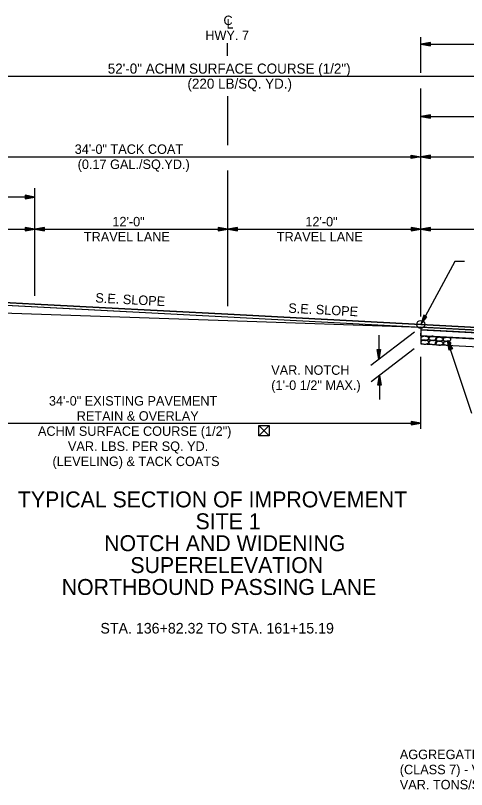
# Model space of a CAD drawing. Extents: x 1398183 to 1398373, y 1967240 to 1968889.
# Drawn here: x 1398229.85 to 1398257.9, y 1968531.11 to 1968579.23 of the extents above; entities that cross this region are included whole.
import ezdxf

# ---------------------------------------------------------------- set-up
doc = ezdxf.new("R2010")
doc.units = 0
for name, color, linetype in [('1', 7, 'Continuous'), ('10', 7, 'Continuous'), ('19', 7, 'Continuous'), ('42', 7, 'Continuous'), ('7', 7, 'Continuous'), ('Level 1', 7, 'Continuous'), ('Level 9', 7, 'Continuous')]:
    doc.layers.add(name, color=color, linetype=linetype)

# ---------------------------------------------------------------- blocks, each defined once
blk = doc.blocks.new('ROCKS')
at = {"layer": '1'}
blk.add_spline([(0.013, 0.06), (0.053, 0.053), (0.107, 0.033), (0.133, 0.013), (0.133, -0.007), (0.12, -0.033), (0.107, -0.04), (0.073, -0.053), (0.033, -0.067), (0.013, -0.067), (-0.02, -0.06), (-0.06, -0.053), (-0.087, -0.047), (-0.113, -0.02), (-0.113, -0.007), (-0.107, 0.02), (-0.087, 0.033), (-0.067, 0.047), (-0.033, 0.053), (-0.02, 0.06), (0.013, 0.06)], degree=3, dxfattribs=at)

msp = doc.modelspace()

# ---------------------------------------------------------------- linework, layer by layer
at = {"layer": '10'}
for p, q in [((1398245.618, 1968553.733), (1398244.977, 1968553.092)), ((1398244.977, 1968553.733), (1398245.618, 1968553.092)), ((1398245.236, 1968553.092), (1398245.225, 1968553.092))]:
    msp.add_line(p, q, dxfattribs=at)
msp.add_lwpolyline([(1398245.225, 1968553.092), (1398244.977, 1968553.092), (1398244.977, 1968553.733), (1398245.618, 1968553.733), (1398245.618, 1968553.092), (1398245.236, 1968553.092)], dxfattribs=at)
at = {"layer": '19'}
for p, q in [((1398255.052, 1968575.667), (1398255.052, 1968577.893)), ((1398255.652, 1968577.55), (1398255.052, 1968577.446)), ((1398255.052, 1968577.446), (1398255.652, 1968577.34)), ((1398255.052, 1968577.446), (1398279.092, 1968577.446)), ((1398255.652, 1968577.495), (1398255.212, 1968577.461)), ((1398255.212, 1968577.431), (1398255.652, 1968577.39)), ((1398255.652, 1968577.34), (1398255.652, 1968577.55)), ((1398272.994, 1968575.446), (1398220.994, 1968575.446)), ((1398255.052, 1968560.522), (1398255.052, 1968574.682)), ((1398255.652, 1968573.05), (1398255.052, 1968572.946)), ((1398255.052, 1968572.946), (1398285.602, 1968572.946)), ((1398255.052, 1968572.946), (1398255.652, 1968572.84)), ((1398255.652, 1968572.995), (1398255.212, 1968572.961)), ((1398255.212, 1968572.931), (1398255.652, 1968572.89)), ((1398255.652, 1968572.84), (1398255.652, 1968573.05)), ((1398220.994, 1968570.446), (1398282.96, 1968570.446)), ((1398254.452, 1968570.341), (1398254.452, 1968570.551)), ((1398254.452, 1968570.551), (1398255.052, 1968570.446)), ((1398254.452, 1968570.496), (1398254.892, 1968570.461)), ((1398255.052, 1968570.446), (1398254.452, 1968570.341)), ((1398254.892, 1968570.431), (1398254.452, 1968570.391)), ((1398255.652, 1968570.551), (1398255.052, 1968570.446)), ((1398255.052, 1968570.446), (1398255.652, 1968570.341)), ((1398255.652, 1968570.496), (1398255.212, 1968570.461)), ((1398255.212, 1968570.431), (1398255.652, 1968570.391)), ((1398255.652, 1968570.341), (1398255.652, 1968570.551)), ((1398231.052, 1968561.794), (1398231.052, 1968568.492)), ((1398231.052, 1968567.946), (1398207.052, 1968567.946)), ((1398230.452, 1968568.051), (1398230.452, 1968567.841)), ((1398231.052, 1968567.946), (1398230.452, 1968568.051)), ((1398230.892, 1968567.961), (1398230.452, 1968567.996)), ((1398230.452, 1968567.841), (1398231.052, 1968567.946)), ((1398230.452, 1968567.891), (1398230.892, 1968567.931)), ((1398221.052, 1968565.946), (1398231.052, 1968565.946)), ((1398230.452, 1968566.051), (1398230.452, 1968565.841)), ((1398231.052, 1968565.946), (1398230.452, 1968566.051)), ((1398230.892, 1968565.961), (1398230.452, 1968565.996)), ((1398230.452, 1968565.841), (1398231.052, 1968565.946)), ((1398230.452, 1968565.891), (1398230.892, 1968565.931)), ((1398231.652, 1968566.05), (1398231.052, 1968565.946)), ((1398231.052, 1968565.946), (1398243.052, 1968565.946)), ((1398231.052, 1968565.946), (1398231.652, 1968565.84)), ((1398231.652, 1968565.995), (1398231.212, 1968565.961)), ((1398231.212, 1968565.931), (1398231.652, 1968565.89)), ((1398231.652, 1968565.84), (1398231.652, 1968566.05)), ((1398242.452, 1968566.051), (1398242.452, 1968565.841)), ((1398243.052, 1968565.946), (1398242.452, 1968566.051)), ((1398242.892, 1968565.961), (1398242.452, 1968565.996)), ((1398242.452, 1968565.841), (1398243.052, 1968565.946)), ((1398242.452, 1968565.891), (1398242.892, 1968565.931)), ((1398243.652, 1968566.05), (1398243.052, 1968565.946)), ((1398243.052, 1968565.946), (1398243.652, 1968565.84)), ((1398243.052, 1968565.946), (1398255.052, 1968565.946)), ((1398243.652, 1968565.995), (1398243.212, 1968565.961)), ((1398243.212, 1968565.931), (1398243.652, 1968565.89)), ((1398243.652, 1968565.84), (1398243.652, 1968566.05)), ((1398254.452, 1968566.051), (1398254.452, 1968565.841)), ((1398255.052, 1968565.946), (1398254.452, 1968566.051)), ((1398254.892, 1968565.961), (1398254.452, 1968565.996)), ((1398254.452, 1968565.841), (1398255.052, 1968565.946)), ((1398254.452, 1968565.891), (1398254.892, 1968565.931)), ((1398255.652, 1968566.05), (1398255.052, 1968565.946)), ((1398255.052, 1968565.946), (1398255.652, 1968565.84)), ((1398255.052, 1968565.946), (1398267.052, 1968565.946)), ((1398255.652, 1968565.995), (1398255.212, 1968565.961)), ((1398255.212, 1968565.931), (1398255.652, 1968565.89)), ((1398255.652, 1968565.84), (1398255.652, 1968566.05)), ((1398255.236, 1968560.602), (1398255.052, 1968560.022)), ((1398255.275, 1968560.578), (1398255.113, 1968560.172)), ((1398255.421, 1968560.506), (1398255.236, 1968560.602)), ((1398255.052, 1968560.022), (1398255.421, 1968560.506)), ((1398255.134, 1968560.158), (1398255.372, 1968560.526)), ((1398255.052, 1968559.856), (1398255.052, 1968559.689)), ((1398255.052, 1968559.689), (1398255.052, 1968559.314)), ((1398255.052, 1968559.689), (1398267.222, 1968559.046)), ((1398266.472, 1968559.085), (1398255.511, 1968559.661)), ((1398254.655, 1968559.55), (1398251.953, 1968557.481)), ((1398252.454, 1968559.365), (1398252.454, 1968557.865)), ((1398255.052, 1968559.314), (1398255.052, 1968558.814)), ((1398267.411, 1968558.667), (1398255.052, 1968559.314)), ((1398256.82, 1968558.432), (1398256.719, 1968559.031)), ((1398256.719, 1968559.031), (1398257.017, 1968558.5)), ((1398258.23, 1968554.496), (1398256.72, 1968559.029)), ((1398256.867, 1968558.449), (1398256.757, 1968558.876)), ((1398256.783, 1968558.885), (1398256.966, 1968558.486)), ((1398254.641, 1968558.511), (1398251.959, 1968556.458)), ((1398252.349, 1968558.465), (1398252.559, 1968558.465)), ((1398252.454, 1968557.865), (1398252.349, 1968558.465)), ((1398252.439, 1968558.025), (1398252.399, 1968558.465)), ((1398252.559, 1968558.465), (1398252.454, 1968557.865)), ((1398252.504, 1968558.465), (1398252.469, 1968558.025)), ((1398257.017, 1968558.5), (1398256.82, 1968558.432)), ((1398255.052, 1968553.529), (1398255.052, 1968558.02)), ((1398252.377, 1968556.254), (1398252.482, 1968556.854)), ((1398252.482, 1968556.854), (1398252.587, 1968556.254)), ((1398252.482, 1968556.854), (1398252.482, 1968555.354)), ((1398252.587, 1968556.254), (1398252.377, 1968556.254)), ((1398252.427, 1968556.254), (1398252.467, 1968556.694)), ((1398252.497, 1968556.694), (1398252.532, 1968556.254)), ((1398221.052, 1968553.88), (1398255.052, 1968553.88)), ((1398254.452, 1968553.985), (1398254.452, 1968553.775)), ((1398255.052, 1968553.88), (1398254.452, 1968553.985)), ((1398254.892, 1968553.895), (1398254.452, 1968553.93)), ((1398254.452, 1968553.775), (1398255.052, 1968553.88)), ((1398254.452, 1968553.825), (1398254.892, 1968553.865))]:
    msp.add_line(p, q, dxfattribs=at)
for points in [[(1398257.777, 1968563.946), (1398257.163, 1968563.946), (1398255.052, 1968560.022)], [(1398220.967, 1968561.654), (1398243.052, 1968560.491), (1398267.137, 1968559.216), (1398273.137, 1968558.898)], [(1398221.052, 1968561.824), (1398231.052, 1968561.294), (1398243.052, 1968560.658), (1398255.052, 1968560.022), (1398267.052, 1968559.386), (1398273.052, 1968559.068)], [(1398255.511, 1968559.661), (1398255.052, 1968559.689), (1398255.046, 1968559.31)], [(1398255.046, 1968559.31), (1398255.626, 1968559.279), (1398266.538, 1968558.715)], [(1398255.052, 1968558.814), (1398267.411, 1968558.167), (1398279.105, 1968557.555)]]:
    msp.add_lwpolyline(points, dxfattribs=at)
for points in [[(1398220.967, 1968561.654), (1398230.818, 1968561.138), (1398243.052, 1968560.491), (1398267.137, 1968559.216), (1398273.137, 1968558.898), (1398273.052, 1968559.068), (1398267.052, 1968559.386), (1398243.052, 1968560.658), (1398231.052, 1968561.294), (1398221.052, 1968561.824)], [(1398255.053, 1968559.856), (1398255.052, 1968559.689), (1398255.876, 1968559.646), (1398264.734, 1968559.177), (1398267.222, 1968559.046), (1398267.137, 1968559.216), (1398266.088, 1968559.271), (1398255.817, 1968559.815)]]:
    msp.add_lwpolyline(points, close=True, dxfattribs=at)
at = {"layer": '42'}
msp.add_lwpolyline([(1398221.052, 1968561.011), (1398243.052, 1968560.263), (1398255.052, 1968559.855)], dxfattribs=at)
at = {"layer": '7'}
for p, q in [((1398243.034, 1968576.725), (1398243.034, 1968577.517)), ((1398243.052, 1968571.163), (1398243.051, 1968574.206)), ((1398243.052, 1968561.158), (1398243.052, 1968569.597))]:
    msp.add_line(p, q, dxfattribs=at)
at = {"layer": 'Level 9'}
msp.add_circle((1398255.052, 1968560.022), 0.25, dxfattribs=at)

# ---------------------------------------------------------------- block references
at = {"layer": 'Level 1'}
for p, xscale, yscale, rotation in [((1398255.286, 1968559.169), 2.011654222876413, 2.0116542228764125, -0.17361855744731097), ((1398255.784, 1968559.167), 2.011654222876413, 2.0116542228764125, -0.17361855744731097), ((1398256.189, 1968559.113), 1.907051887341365, 1.9070518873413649, -0.173618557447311), ((1398256.665, 1968559.101), 1.9598639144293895, 1.959863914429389, -0.173618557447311), ((1398255.277, 1968558.927), 2.011654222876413, 2.0116542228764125, -0.17361855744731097), ((1398255.781, 1968558.909), 2.011654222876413, 2.0116542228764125, -0.17361855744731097), ((1398256.18, 1968558.866), 1.9974694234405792, 1.9974694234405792, -0.17361855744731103), ((1398256.677, 1968558.857), 1.890205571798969, 1.8902055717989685, -0.17361855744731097)]:
    msp.add_blockref('ROCKS', p, dxfattribs=dict(at, xscale=xscale, yscale=yscale, rotation=rotation))

# ---------------------------------------------------------------- texts
at = {"layer": '10'}
for s, height, p in [('12\'-0"', 0.59, (1398235.874, 1968566.121)), ('12\'-0"', 0.59, (1398247.874, 1968566.121)), ('TRAVEL LANE', 0.59001, (1398234.102, 1968565.181)), ('TRAVEL LANE', 0.59001, (1398246.102, 1968565.181)), ('VAR. NOTCH', 0.59, (1398245.754, 1968556.892)), ('(1\'-0 1/2" MAX.)', 0.59001, (1398245.754, 1968555.952))]:
    msp.add_text(s, height=height, dxfattribs=at).set_placement(p)
for s, p in [('34\'-0" EXISTING PAVEMENT', (1398231.928, 1968554.978)), ('RETAIN & OVERLAY', (1398233.658, 1968554.038)), ('ACHM SURFACE COURSE (1/2")', (1398231.247, 1968553.098)), ('VAR. LBS. PER SQ. YD.', (1398233.11, 1968552.158)), ('(LEVELING) & TACK COATS', (1398232.149, 1968551.218))]:
    msp.add_text(s, height=0.59001, rotation=0, dxfattribs=at).set_placement(p)
at = {"layer": '19'}
for s, height, p in [('C', 0.59, (1398242.783, 1968578.633)), ('L', 0.59, (1398242.971, 1968578.422)), ('HWY. 7', 0.59, (1398241.652, 1968577.703)), ('52\'-0" ACHM SURFACE COURSE (1/2")', 0.625, (1398235.587, 1968575.617)), ('(220 LB/SQ. YD.)', 0.625, (1398240.543, 1968574.68)), ('TYPICAL SECTION OF IMPROVEMENT', 0.98999, (1398229.999, 1968548.651)), ('SITE 1', 0.99, (1398241.048, 1968547.29)), ('NOTCH AND WIDENING', 0.98999, (1398235.362, 1968545.929)), ('SUPERELEVATION', 0.98999, (1398236.991, 1968544.568)), ('NORTHBOUND PASSING LANE', 0.98999, (1398232.723, 1968543.206)), ('STA. 136+82.32 TO STA. 161+15.19', 0.65999, (1398235.129, 1968540.807))]:
    msp.add_text(s, height=height, dxfattribs=at).set_placement(p)
for s, height, rotation, p in [('S.E. SLOPE', 0.59, 356.9662, (1398234.804, 1968561.391)), ('S.E. SLOPE', 0.59, 356.9662, (1398246.804, 1968560.755)), ('AGGREGATE BASE COURSE', 0.59001, 360, (1398253.749, 1968532.998)), ('(CLASS 7) - VAR. COMPACTED DEPTH', 0.59001, 360, (1398253.749, 1968532.058)), ('VAR. TONS/STA.', 0.59001, 360, (1398253.749, 1968531.118))]:
    msp.add_text(s, height=height, rotation=rotation, dxfattribs=at).set_placement(p)
at = {"layer": '42'}
for s, p in [('34\'-0" TACK COAT', (1398233.53, 1968570.626)), ('(0.17 GAL./SQ.YD.)', (1398233.714, 1968569.686))]:
    msp.add_text(s, height=0.59001, rotation=360, dxfattribs=at).set_placement(p)

doc.saveas('drawing.dxf')
